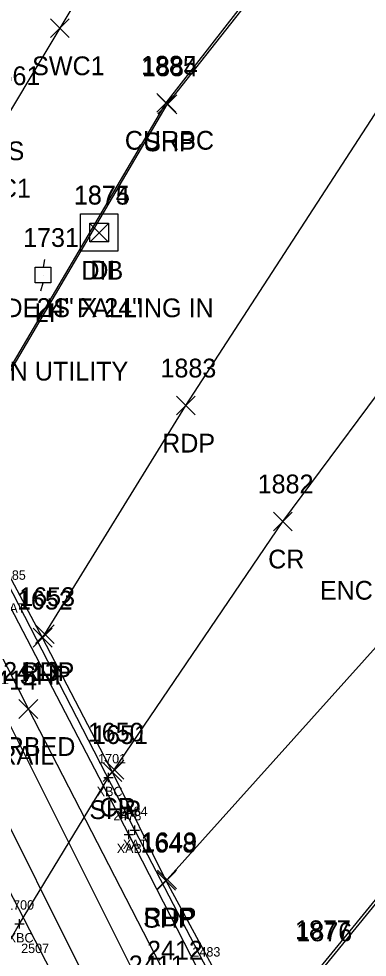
# Model space of a CAD drawing. Extents: x 1462668 to 1465147, y 550359 to 557351.
# Drawn here: x 1464688.2 to 1464725.3, y 552631.2 to 552731.2 of the extents above; entities that cross this region are included whole.
import ezdxf

# ---------------------------------------------------------------- set-up
doc = ezdxf.new("R2010")
doc.units = 0
for name, color, linetype in [('B_A', 7, 'Continuous'), ('B_I', 7, 'Continuous'), ('B_TIC', 7, 'Continuous'), ('BELB', 7, 'Continuous'), ('BSUBM', 7, 'Continuous'), ('D_A', 7, 'Continuous'), ('D_C', 7, 'Continuous'), ('D_I', 7, 'Continuous'), ('D_TIC', 7, 'Continuous'), ('DS', 7, 'Continuous'), ('L_A', 7, 'Continuous'), ('L_I', 7, 'Continuous'), ('P_A', 7, 'Continuous'), ('P_I', 7, 'Continuous'), ('P_TIC', 7, 'Continuous'), ('PET', 7, 'Continuous'), ('PRC', 7, 'Continuous'), ('PSP', 7, 'Continuous'), ('R_A', 7, 'Continuous'), ('R_I', 7, 'Continuous'), ('R_TIC', 7, 'Continuous'), ('RC', 7, 'Continuous'), ('RR', 7, 'Continuous'), ('RRB', 7, 'Continuous'), ('RSW', 7, 'Continuous'), ('U_A', 7, 'Continuous'), ('U_C', 7, 'Continuous'), ('U_I', 7, 'Continuous'), ('ULP', 7, 'Continuous')]:
    doc.layers.add(name, color=color, linetype=linetype)

msp = doc.modelspace()

# ---------------------------------------------------------------- linework, layer by layer
at = {"layer": 'B_TIC'}
for p, q in [((1464697.74, 552650.33), (1464697.81, 552650.33)), ((1464699.89, 552644.26), (1464699.97, 552644.26)), ((1464700.56, 552644.71), (1464700.63, 552644.71)), ((1464688.25, 552634.74), (1464688.33, 552634.74))]:
    msp.add_line(p, q, dxfattribs=at)
for points in [[(1464697.73, 552649.83), (1464697.73, 552650.83)], [(1464697.23, 552650.33), (1464698.23, 552650.33)], [(1464700.55, 552644.21), (1464700.55, 552645.21)], [(1464699.39, 552644.26), (1464700.39, 552644.26)], [(1464699.89, 552643.76), (1464699.89, 552644.76)], [(1464700.05, 552644.71), (1464701.05, 552644.71)], [(1464688.25, 552634.24), (1464688.25, 552635.24)], [(1464687.75, 552634.74), (1464688.75, 552634.74)]]:
    msp.add_lwpolyline(points, dxfattribs=at)
at = {"layer": 'BELB'}
msp.add_lwpolyline([(1464682.49, 552624.75), (1464688.25, 552634.74), (1464697.73, 552650.33)], dxfattribs=at)
at = {"layer": 'BSUBM'}
for points in [[(1464723.04, 552601.4), (1464713.03, 552620.25), (1464708.31, 552629.74), (1464700.55, 552644.71), (1464687.57, 552669.89), (1464678.36, 552688.15)], [(1464722.84, 552599.91), (1464712.42, 552619.85), (1464699.89, 552644.26), (1464686.83, 552669.36), (1464677.44, 552687.54)]]:
    msp.add_lwpolyline(points, dxfattribs=at)
at = {"layer": 'D_TIC'}
for points in [[(1464695.74, 552707.37), (1464697.74, 552709.37)], [(1464697.74, 552707.37), (1464695.74, 552709.37)]]:
    msp.add_lwpolyline(points, dxfattribs=at)
at = {"layer": 'DS'}
for p, q in [((1464694.73, 552710.4), (1464698.73, 552710.4)), ((1464694.73, 552706.4), (1464694.73, 552710.4)), ((1464698.73, 552710.4), (1464698.73, 552706.4)), ((1464695.73, 552707.4), (1464695.73, 552709.4)), ((1464695.73, 552709.4), (1464697.73, 552709.4)), ((1464697.73, 552709.4), (1464697.73, 552707.4)), ((1464696.74, 552708.4), (1464696.74, 552708.4)), ((1464696.74, 552708.4), (1464696.74, 552708.4)), ((1464697.73, 552707.4), (1464695.73, 552707.4)), ((1464698.73, 552706.4), (1464694.73, 552706.4))]:
    msp.add_line(p, q, dxfattribs=at)
at = {"layer": 'P_TIC'}
for points in [[(1464703, 552721.05), (1464705, 552723.05)], [(1464705, 552721.05), (1464703, 552723.05)], [(1464704.97, 552688.95), (1464706.97, 552690.95)], [(1464706.97, 552688.95), (1464704.97, 552690.95)], [(1464715.32, 552676.6), (1464717.32, 552678.6)], [(1464717.32, 552676.6), (1464715.32, 552678.6)], [(1464689.71, 552664.22), (1464691.71, 552666.22)], [(1464691.71, 552664.22), (1464689.71, 552666.22)], [(1464689.95, 552664.59), (1464691.95, 552666.59)], [(1464691.95, 552664.59), (1464689.95, 552666.59)], [(1464697.15, 552649.89), (1464699.15, 552651.89)], [(1464699.15, 552649.89), (1464697.15, 552651.89)], [(1464697.35, 552650.15), (1464699.35, 552652.15)], [(1464699.35, 552650.15), (1464697.35, 552652.15)], [(1464702.88, 552638.32), (1464704.88, 552640.32)], [(1464704.88, 552638.32), (1464702.88, 552640.32)], [(1464702.97, 552638.46), (1464704.97, 552640.46)], [(1464704.97, 552638.46), (1464702.97, 552640.46)]]:
    msp.add_lwpolyline(points, dxfattribs=at)
at = {"layer": 'PET'}
for points in [[(1464690.95, 552665.59), (1464705.97, 552689.95), (1464730.95, 552728.42), (1464756.78, 552757.93), (1464781.56, 552791.49), (1464804.1, 552812.88), (1464834.32, 552847.22), (1464855.04, 552863.89), (1464867.1, 552873.05), (1464879.3, 552886.59)], [(1464703.97, 552639.46), (1464728.77, 552667.06), (1464755.9, 552707.97), (1464789.54, 552743.55), (1464807.6, 552768.88), (1464825.2, 552787.71), (1464842.93, 552809.98), (1464865.69, 552832.75), (1464880.58, 552846.68), (1464904.1, 552869.16)]]:
    msp.add_lwpolyline(points, dxfattribs=at)
at = {"layer": 'PRC'}
msp.add_lwpolyline([(1464698.35, 552651.15), (1464716.32, 552677.6), (1464744.52, 552715.54), (1464772.1, 552750.17), (1464779.18, 552759.11), (1464796.25, 552779.04), (1464814.91, 552799.8), (1464849.7, 552834.84), (1464867.53, 552848.82), (1464892.14, 552871.14)], dxfattribs=at)
at = {"layer": 'PSP'}
for points in [[(1464713.42, 552621.66), (1464703.88, 552639.32), (1464698.15, 552650.89), (1464690.71, 552665.22), (1464681.1, 552683.16), (1464704, 552722.05), (1464716.48, 552737.91), (1464734.78, 552760.75), (1464735.82, 552761.92), (1464745.24, 552772.27), (1464746.27, 552773.34), (1464761.55, 552790.01), (1464762.97, 552792.1), (1464763.76, 552794.25), (1464784.89, 552812.77), (1464795.31, 552821.35), (1464823.73, 552847.99), (1464827.49, 552852.41)], [(1464713.64, 552621.47), (1464720.3, 552630.09), (1464743.11, 552657.96), (1464771.73, 552693.19), (1464802.94, 552732.09), (1464806.7, 552736.72), (1464807.51, 552737.69), (1464827.96, 552762.61), (1464840.31, 552778.01), (1464860.3, 552803.04), (1464847.06, 552806.2), (1464846.96, 552807.41), (1464865.09, 552816), (1464884.93, 552820.04), (1464894.44, 552821.2), (1464905.2, 552819.49), (1464914.43, 552816.32), (1464923.05, 552811.38)]]:
    msp.add_lwpolyline(points, dxfattribs=at)
at = {"layer": 'R_TIC'}
for points in [[(1464691.55, 552729.16), (1464693.55, 552731.16)], [(1464693.55, 552729.16), (1464691.55, 552731.16)], [(1464702.89, 552721.22), (1464704.89, 552723.22)], [(1464704.89, 552721.22), (1464702.89, 552723.22)], [(1464688.19, 552656.62), (1464690.19, 552658.62)], [(1464690.19, 552656.62), (1464688.19, 552658.62)]]:
    msp.add_lwpolyline(points, dxfattribs=at)
at = {"layer": 'RC'}
for points in [[(1464714.1, 552621.11), (1464713.72, 552621.38), (1464720.51, 552629.87), (1464743.2, 552657.68), (1464745.71, 552660.87), (1464771.87, 552693.09), (1464801.88, 552730.35), (1464803.14, 552731.98), (1464806.82, 552736.57), (1464807.62, 552737.53), (1464827.98, 552762.36), (1464840.55, 552777.99), (1464860.73, 552803.16), (1464848.01, 552806.27), (1464847.4, 552807.43), (1464865.21, 552815.86), (1464884.88, 552819.62), (1464894.44, 552820.83), (1464904.96, 552819.1), (1464914.17, 552815.93), (1464922.75, 552811.24)], [(1464681.03, 552683.44), (1464703.89, 552722.22), (1464716.21, 552738.06), (1464734.65, 552760.88), (1464735.67, 552761.97), (1464745.17, 552772.41), (1464746.11, 552773.42), (1464761.32, 552790.16), (1464762.7, 552792.22), (1464763.56, 552794.28), (1464763.47, 552797.08), (1464762.5, 552800.03), (1464761.27, 552802.91), (1464759.4, 552805.48), (1464759.23, 552805.34)]]:
    msp.add_lwpolyline(points, dxfattribs=at)
at = {"layer": 'RR'}
for points in [[(1464849.39, 552249.53), (1464842.82, 552270.79), (1464835.11, 552294.84), (1464826.26, 552322.52), (1464813.91, 552358.25), (1464808.67, 552373.87), (1464804.99, 552384.75), (1464790.19, 552425.01), (1464777.18, 552458.67), (1464762.36, 552494.61), (1464744.91, 552535.15), (1464735.63, 552555.85), (1464721.29, 552586.6), (1464702.02, 552626.35), (1464686.84, 552656.69), (1464671.35, 552687.14), (1464662.33, 552704.74), (1464642.53, 552744.08), (1464629.16, 552771.13), (1464613.48, 552803.16), (1464601.34, 552828.32)], [(1464844.81, 552247.75), (1464838.18, 552269.15), (1464830.39, 552293.62), (1464821.39, 552321.55), (1464809.52, 552356.64), (1464804.15, 552372.47), (1464800.3, 552383.08), (1464785.6, 552423.21), (1464772.72, 552456.47), (1464757.81, 552492.7), (1464740.23, 552533.39), (1464731.22, 552553.66), (1464716.74, 552584.61), (1464697.67, 552624.11), (1464682.45, 552654.5), (1464666.88, 552684.94), (1464657.73, 552702.87), (1464638.13, 552741.98), (1464624.71, 552769), (1464609.23, 552800.97), (1464596.7, 552826.14)]]:
    msp.add_lwpolyline(points, dxfattribs=at)
at = {"layer": 'RRB'}
for points in [[(1464851.04, 552250.44), (1464845.15, 552271.64), (1464837.54, 552295.46), (1464828.77, 552323.58), (1464816.78, 552359.11), (1464810.93, 552374.77), (1464807.84, 552386.03), (1464792.77, 552426.04), (1464778.94, 552461.75), (1464771.17, 552477.61), (1464764.62, 552495.61), (1464747.04, 552536.3), (1464737.62, 552557.17), (1464723.44, 552587.94), (1464704.53, 552627.92), (1464689.19, 552657.62), (1464673.57, 552688.33), (1464664.01, 552705.15), (1464644.5, 552745.11), (1464631.56, 552772.37), (1464615.64, 552804.18), (1464603.91, 552829.42)], [(1464842.44, 552246.93), (1464836.49, 552268.55), (1464828.07, 552292.9), (1464819.09, 552320.89), (1464807.29, 552355.87), (1464801.46, 552371.53), (1464797.6, 552381.72), (1464783.01, 552422.47), (1464769.41, 552454.58), (1464755.32, 552491.81), (1464738.61, 552532.38), (1464729.39, 552552.76), (1464715, 552583.84), (1464695.07, 552622.98), (1464679.55, 552653), (1464663.95, 552683.28), (1464654.86, 552701.9), (1464635.34, 552740.46), (1464622.38, 552767.72), (1464607.07, 552799.75), (1464594.74, 552825)]]:
    msp.add_lwpolyline(points, dxfattribs=at)
at = {"layer": 'RSW'}
msp.add_lwpolyline([(1464703.98, 552749.32), (1464692.55, 552730.16), (1464684.69, 552717.12), (1464682.42, 552713.18), (1464676.9, 552703.42), (1464680.62, 552701.19), (1464675.92, 552692.62)], dxfattribs=at)
at = {"layer": 'ULP'}
for p, q in [((1464690.92, 552705.53), (1464690.75, 552704.69)), ((1464689.92, 552703.03), (1464689.92, 552704.69)), ((1464689.92, 552704.69), (1464691.58, 552704.69)), ((1464690.75, 552703.86), (1464690.75, 552703.86)), ((1464691.58, 552704.69), (1464691.58, 552703.03)), ((1464691.58, 552703.03), (1464689.92, 552703.03)), ((1464690.5, 552702.19), (1464690.75, 552703.03))]:
    msp.add_line(p, q, dxfattribs=at)

# ---------------------------------------------------------------- texts
at = {"layer": 'B_A'}
for s, p in [('XAT', (1464686.27, 552667.89)), ('XBC', (1464696.47, 552648.33)), ('XAB', (1464698.61, 552642.26)), ('XAT', (1464699.26, 552642.71)), ('XBC', (1464686.99, 552632.74))]:
    msp.add_text(s, height=1, dxfattribs=at).set_placement(p)
at = {"layer": 'B_I'}
for s, p in [('2485', (1464685.94, 552671.39)), ('1701', (1464696.63, 552651.83)), ('2478', (1464698.26, 552645.76)), ('2484', (1464698.92, 552646.21)), ('1700', (1464686.82, 552636.24)), ('2507', (1464688.42, 552631.61)), ('2483', (1464706.68, 552631.24))]:
    msp.add_text(s, height=1, dxfattribs=at).set_placement(p)
at = {"layer": 'D_A'}
for s, p in [('DIB', (1464694.84, 552703.37)), ('DI', (1464695.79, 552703.4))]:
    msp.add_text(s, height=2, dxfattribs=at).set_placement(p)
at = {"layer": 'D_C'}
for s, p in [('INSIDE IS FALLING IN', (1464681.44, 552699.37)), ('24" X 24"', (1464690.09, 552699.4)), ('ENCLOSED PIPE THAT FLOWS DOWN', (1464720.26, 552669.27))]:
    msp.add_text(s, height=2, dxfattribs=at).set_placement(p)
at = {"layer": 'D_I'}
for s, p in [('1874', (1464694.04, 552711.4)), ('1875', (1464694.05, 552711.37))]:
    msp.add_text(s, height=2, dxfattribs=at).set_placement(p)
at = {"layer": 'L_A'}
msp.add_text('BS', height=2, dxfattribs=at).set_placement((1464685.19, 552716.1))
at = {"layer": 'L_I'}
msp.add_text('1661', height=2, dxfattribs=at).set_placement((1464684.52, 552724.1))
at = {"layer": 'P_A'}
for s, p in [('SHP', (1464701.53, 552717.05)), ('RDP', (1464703.45, 552684.95)), ('CR', (1464714.75, 552672.6)), ('SHP', (1464688.24, 552660.22)), ('RDP', (1464688.44, 552660.59)), ('SHP', (1464695.69, 552645.89)), ('CR', (1464696.78, 552646.15)), ('SHP', (1464701.42, 552634.32)), ('RDP', (1464701.46, 552634.46))]:
    msp.add_text(s, height=2, dxfattribs=at).set_placement(p)
at = {"layer": 'P_I'}
for s, p in [('1884', (1464701.31, 552725.05)), ('1883', (1464703.27, 552692.95)), ('1882', (1464713.63, 552680.6)), ('1652', (1464687.97, 552668.22)), ('1653', (1464688.21, 552668.59)), ('1650', (1464695.52, 552654.15)), ('1651', (1464695.98, 552653.89)), ('1648', (1464701.14, 552642.32)), ('1649', (1464701.22, 552642.46)), ('1877', (1464717.61, 552633.09))]:
    msp.add_text(s, height=2, dxfattribs=at).set_placement(p)
at = {"layer": 'R_A'}
for s, p in [('SWC1', (1464689.59, 552725.16)), ('CURBC', (1464699.47, 552717.22)), ('SWC1', (1464681.73, 552712.12)), ('RRBED', (1464684.84, 552652.62)), ('RRRAIL', (1464682.13, 552651.69))]:
    msp.add_text(s, height=2, dxfattribs=at).set_placement(p)
at = {"layer": 'R_I'}
for s, p in [('1885', (1464701.2, 552725.22)), ('2413', (1464686.5, 552660.62)), ('2414', (1464684.15, 552659.69)), ('1876', (1464717.76, 552632.87)), ('2412', (1464701.84, 552630.92)), ('2411', (1464699.89, 552629.35))]:
    msp.add_text(s, height=2, dxfattribs=at).set_placement(p)
at = {"layer": 'U_A'}
msp.add_text('LI', height=2, dxfattribs=at).set_placement((1464689.85, 552698.86))
at = {"layer": 'U_C'}
msp.add_text('BOX COVERING UNKNOWN UTILITY', height=2, dxfattribs=at).set_placement((1464653.62, 552692.62))
at = {"layer": 'U_I'}
msp.add_text('1731', height=2, dxfattribs=at).set_placement((1464688.63, 552706.86))

doc.saveas('drawing.dxf')
